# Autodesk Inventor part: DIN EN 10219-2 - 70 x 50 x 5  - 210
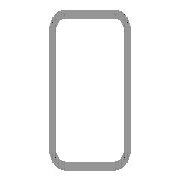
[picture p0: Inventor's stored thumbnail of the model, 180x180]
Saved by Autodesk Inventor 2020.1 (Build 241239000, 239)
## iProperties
Created: 2019-01
Part Number: DIN EN 10219-2 - 70 x 50 x 5  - 210
Material: Stahl, weich
Description: Kaltgeformte, geschweißte Baustahl-Hohlprofile aus unlegiertem Feinkorn-Baustahl
Document SubType Name: Modeling
Standard: DIN
Designer: lutzd
Standard Revision: 2006-07
Standards Organization: DIN
Language: de-DE
Size Designation: 70 x 50 x 5
Categories: <MemberInstance><Categories><Category DisplayName="Profile" InternalName="089c4875-fa83-4c05-b084-43b9cc11f5ed" Mnemonic="GRDR"><CategoryParameter DisplayName="
Stock Number: 70 x 50 x 5
Mass: 1704.49 g
Surface Area: 891.333 cm^2
Volume: 217.133 cm^3
Density: 7.85 g/cm^3
Appearance: Halbpoliert
_CCFamilyMember: 17
_CCFamilyDisplayName: DIN EN 10219-2 (Rechteckiges Hohlprofil - Kaltgeformt) - Kaltgeformte, geschweißte Baustahl-Hohlprofile aus unlegiertem Feinkorn-Baustahl
_FrameMemberDoc: Frame Member File
_Version: 15.0.0
_GetPNFromCC: 1
G_L: 210,000 mm
G_W: 50,000 mm
G_H: 70,000 mm
DocNumber: ADSK-014136
Folder: .
Dimensions: 50x70x210 mm
Mass: 1,704 kg
+FECDEF38-5C3F-4886-88E5-45ABCA007BA9+SCHNITTDETAIL1: Schnittwinkel 90,00 grd
IsCustomPart: 1
Title: Profil-Bauteil
Author: lutzd
Revision Number: -
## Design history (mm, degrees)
node "Startebene"
node "Endebene"
sketch "Skizze"
  geometry: L1 (-25, -25)-(-25, 25); L2 (-15, 35)-(15, 35); L3 (25, 25)-(25, -25); L4 (15, -35)-(-15, -35); L5 (-15, 30)-(15, 30); L6 (20, 25)-(20, -25); L7 (15, -30)-(-15, -30); L8 (-20, -25)-(-20, 25); L9 (0, 51.899)-(0, -51.899) reference; L10 (-37.899, 0)-(37.899, 0) reference; A1 r 10 centre (-15, -25) between (-25, -25) and (-15, -35); A2 r 10 centre (-15, 25) between (-15, 35) and (-25, 25); A3 r 10 centre (15, 25) between (25, 25) and (15, 35); A4 r 10 centre (15, -25) between (15, -35) and (25, -25); A5 r 5 centre (-15, 25) between (-15, 30) and (-20, 25); A6 r 5 centre (15, 25) between (20, 25) and (15, 30); A7 r 5 centre (15, -25) between (15, -30) and (20, -25); A8 r 5 centre (-15, -25) between (-20, -25) and (-15, -30)
  constraints: 16 end point, 16 point on circle, 8 centre point, 8 tangent, 4 parallel, 3 equal radius, 2 perpendicular, 7 other
  dimensions: "d7" = 10 radius of A1 (= G_IR); "d10" = 70 distance between parallel lines of L2 L4 (= G_H); "d11" = 50 distance between parallel lines of L1 L3 (= G_W); "d12" = 5 distance between parallel lines of L3 L6 (= G_T); "d15" = 35 distance between parallel lines of L2 L10 (= 0.5 x d10); "d16" = 25 distance between parallel lines of L9 L3 (= 0.5 x d11)
extrude "Körper" new body sketch "Skizze" stored distance "d3" = 210 (= G_L); taper "d4" = 0 deg
node "Driven Length"
  sketch "Sketch3"
    geometry: L1 (0, 0)-(10, 0) reference
    constraints: 2 end point, 1 horizontal
  workplane "Work Plane3"
  sketch "Sketch4"
    geometry: L1 (-2, 50)-(12, 50) reference; L2 (-2, 260)-(12, 260) reference
    dimensions: "d18" = 210 distance between parallel lines of L1 L2 (derived)
workplane "Arbeitsebene4"
feature "Trennen1"
sketch "Skizze5"
  geometry: L1 (210, -50)-(210, 0) reference; L2 (0, -60)-(210, -60) reference; L3 (210, -19)-(104, -19); 3 further points
  constraints: 2 end point, 2 point on line, 1 coincident, 1 horizontal
  dimensions: "d19" = 41 distance between parallel lines of L2 L3; "d20" = 90 distance of point (194, -19) point (104, -19); "d21" = 16 distance from line of L1 point (194, -19)
hole "Bohrung1" sketch "Skizze5" at (194, -19), (104, -19) diameter "d22" = 6.647; stored, may be unused: countersink angle "d26" = 90 deg, drill point angle "d28" = 118 deg; dims "d23" = 16, "d24" = 4, "d25" = 2, "d27" = 8
body "Solid1"
other parameters: "G_W" = 50 [user parameter; used in 1 equation term], "G_H" = 70 [user parameter; used in 1 equation term], "G_T" = 5 [user parameter; used in 1 equation term], "G_IR" = 10 [user parameter; used in 1 equation term], "G_L" = 210 (= d18) [user parameter; used in 1 equation term], "G_OFFSET_END" = 0 [user parameter; used in 1 equation term], "d17" = 90 deg
